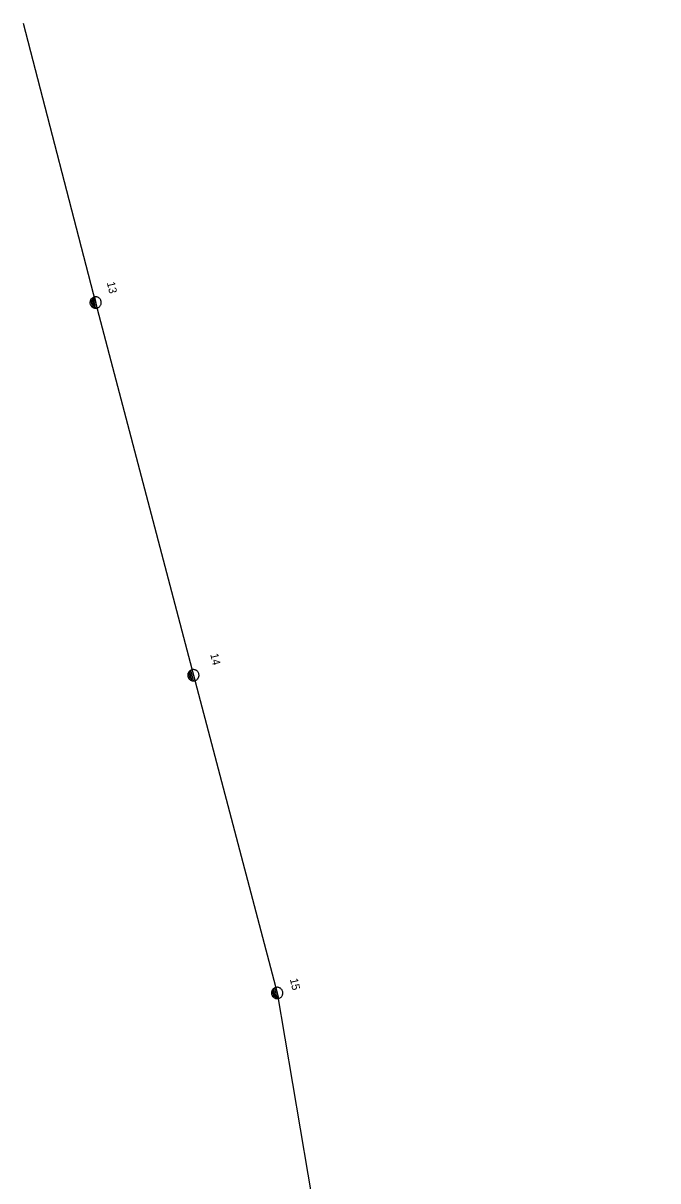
# Model space of a CAD drawing. Extents: x -762349 to -761250, y -1154000 to -1153000.
# Drawn here: x -761620.3 to -761482.3, y -1153251.6 to -1153000 of the extents above; entities that cross this region are included whole.
import ezdxf

# ---------------------------------------------------------------- set-up
doc = ezdxf.new("R2010")
doc.units = 0
for name, color, linetype in [('Vrstva 1', 7, 'Continuous'), ('Vrstva 13', 7, 'Continuous'), ('Vrstva 14', 7, 'Continuous')]:
    doc.layers.add(name, color=color, linetype=linetype)

msp = doc.modelspace()

# ---------------------------------------------------------------- linework, layer by layer
at = {"layer": 'Vrstva 1'}
msp.add_lwpolyline([(-761620.31, -1153000), (-761604.55, -1153060.72), (-761583.29, -1153141.72), (-761565.07, -1153210.77), (-761553.44, -1153279.72), (-761539.9, -1153359.95), (-761527.93, -1153428.59), (-761516.72, -1153491.97), (-761505.02, -1153559.26), (-761494.37, -1153619.64), (-761482.3, -1153689.6)], dxfattribs=at)
at = {"layer": 'Vrstva 13'}
for points in [[(-761604.279, -1153061.908), (-761604.155, -1153061.873), (-761604.036, -1153061.825), (-761603.922, -1153061.764), (-761603.815, -1153061.693), (-761603.717, -1153061.61), (-761603.628, -1153061.517), (-761603.549, -1153061.416), (-761603.48, -1153061.308), (-761603.424, -1153061.192), (-761603.38, -1153061.071), (-761603.349, -1153060.946), (-761603.331, -1153060.819), (-761603.327, -1153060.69), (-761603.336, -1153060.562), (-761603.358, -1153060.435), (-761603.393, -1153060.312), (-761603.442, -1153060.193), (-761603.502, -1153060.079), (-761603.574, -1153059.973), (-761603.656, -1153059.874), (-761603.749, -1153059.785), (-761603.85, -1153059.705), (-761603.959, -1153059.637), (-761604.075, -1153059.581), (-761604.196, -1153059.537), (-761604.32, -1153059.506), (-761604.448, -1153059.488), (-761604.576, -1153059.483), (-761604.704, -1153059.492), (-761604.831, -1153059.515), (-761604.955, -1153059.55), (-761605.074, -1153059.598), (-761605.188, -1153059.659), (-761605.294, -1153059.731), (-761605.393, -1153059.814), (-761605.482, -1153059.906), (-761605.561, -1153060.007), (-761605.629, -1153060.116), (-761605.686, -1153060.232), (-761605.73, -1153060.352), (-761605.761, -1153060.478), (-761605.779, -1153060.604), (-761605.783, -1153060.733), (-761605.774, -1153060.862), (-761605.752, -1153060.988), (-761605.716, -1153061.112), (-761605.668, -1153061.231), (-761605.608, -1153061.344), (-761605.536, -1153061.451), (-761605.453, -1153061.549), (-761605.361, -1153061.639), (-761605.259, -1153061.718), (-761605.15, -1153061.786), (-761605.035, -1153061.842), (-761604.914, -1153061.886), (-761604.789, -1153061.918), (-761604.662, -1153061.935), (-761604.533, -1153061.94), (-761604.405, -1153061.931), (-761604.279, -1153061.908)], [(-761605.39, -1153059.876), (-761604.945, -1153061.803)], [(-761605.148, -1153059.643), (-761604.634, -1153061.869)], [(-761604.824, -1153059.51), (-761604.272, -1153061.903)], [(-761605.61, -1153060.203), (-761605.29, -1153061.587)], [(-761583.019, -1153142.908), (-761582.895, -1153142.873), (-761582.776, -1153142.825), (-761582.662, -1153142.764), (-761582.555, -1153142.693), (-761582.457, -1153142.61), (-761582.368, -1153142.518), (-761582.289, -1153142.416), (-761582.22, -1153142.308), (-761582.164, -1153142.192), (-761582.12, -1153142.071), (-761582.089, -1153141.946), (-761582.071, -1153141.819), (-761582.067, -1153141.69), (-761582.076, -1153141.562), (-761582.098, -1153141.435), (-761582.133, -1153141.312), (-761582.182, -1153141.193), (-761582.242, -1153141.079), (-761582.314, -1153140.973), (-761582.396, -1153140.874), (-761582.489, -1153140.785), (-761582.59, -1153140.705), (-761582.7, -1153140.637), (-761582.815, -1153140.581), (-761582.936, -1153140.537), (-761583.06, -1153140.506), (-761583.188, -1153140.488), (-761583.316, -1153140.483), (-761583.445, -1153140.492), (-761583.571, -1153140.515), (-761583.695, -1153140.55), (-761583.814, -1153140.598), (-761583.928, -1153140.659), (-761584.034, -1153140.731), (-761584.133, -1153140.814), (-761584.222, -1153140.906), (-761584.301, -1153141.007), (-761584.369, -1153141.116), (-761584.426, -1153141.232), (-761584.47, -1153141.353), (-761584.501, -1153141.478), (-761584.519, -1153141.604), (-761584.523, -1153141.733), (-761584.514, -1153141.862), (-761584.492, -1153141.988), (-761584.456, -1153142.112), (-761584.408, -1153142.231), (-761584.348, -1153142.344), (-761584.276, -1153142.451), (-761584.194, -1153142.549), (-761584.101, -1153142.639), (-761583.999, -1153142.718), (-761583.89, -1153142.786), (-761583.775, -1153142.842), (-761583.654, -1153142.886), (-761583.53, -1153142.918), (-761583.402, -1153142.935), (-761583.273, -1153142.94), (-761583.145, -1153142.931), (-761583.019, -1153142.908)], [(-761583.565, -1153140.51), (-761583.012, -1153142.903)], [(-761584.35, -1153141.203), (-761584.03, -1153142.587)], [(-761584.13, -1153140.876), (-761583.685, -1153142.803)], [(-761583.888, -1153140.643), (-761583.374, -1153142.869)], [(-761564.799, -1153211.958), (-761564.675, -1153211.923), (-761564.556, -1153211.875), (-761564.442, -1153211.814), (-761564.335, -1153211.743), (-761564.237, -1153211.66), (-761564.148, -1153211.568), (-761564.069, -1153211.466), (-761564, -1153211.358), (-761563.944, -1153211.242), (-761563.9, -1153211.121), (-761563.869, -1153210.996), (-761563.851, -1153210.869), (-761563.847, -1153210.74), (-761563.856, -1153210.612), (-761563.878, -1153210.485), (-761563.913, -1153210.362), (-761563.962, -1153210.243), (-761564.022, -1153210.129), (-761564.094, -1153210.023), (-761564.176, -1153209.924), (-761564.269, -1153209.835), (-761564.37, -1153209.755), (-761564.48, -1153209.687), (-761564.595, -1153209.631), (-761564.716, -1153209.587), (-761564.84, -1153209.556), (-761564.968, -1153209.538), (-761565.096, -1153209.533), (-761565.225, -1153209.542), (-761565.351, -1153209.565), (-761565.475, -1153209.6), (-761565.594, -1153209.648), (-761565.708, -1153209.709), (-761565.814, -1153209.781), (-761565.913, -1153209.864), (-761566.002, -1153209.956), (-761566.081, -1153210.057), (-761566.149, -1153210.166), (-761566.206, -1153210.282), (-761566.25, -1153210.403), (-761566.281, -1153210.528), (-761566.299, -1153210.654), (-761566.303, -1153210.783), (-761566.294, -1153210.912), (-761566.272, -1153211.038), (-761566.236, -1153211.162), (-761566.188, -1153211.281), (-761566.128, -1153211.394), (-761566.056, -1153211.501), (-761565.974, -1153211.599), (-761565.881, -1153211.689), (-761565.779, -1153211.768), (-761565.67, -1153211.836), (-761565.555, -1153211.892), (-761565.434, -1153211.936), (-761565.31, -1153211.968), (-761565.182, -1153211.985), (-761565.053, -1153211.99), (-761564.925, -1153211.981), (-761564.799, -1153211.958)], [(-761566.13, -1153210.253), (-761565.81, -1153211.637)], [(-761565.91, -1153209.926), (-761565.465, -1153211.853)], [(-761565.668, -1153209.693), (-761565.154, -1153211.919)], [(-761565.344, -1153209.56), (-761564.792, -1153211.953)]]:
    msp.add_lwpolyline(points, dxfattribs=at)

# ---------------------------------------------------------------- texts
at = {"layer": 'Vrstva 14'}
for s, p in [('13', (-761602.12, -1153056.38)), ('14', (-761579.63, -1153137.16)), ('15', (-761562.32, -1153207.78))]:
    msp.add_text(s, height=1.74, rotation=283, dxfattribs=at).set_placement(p)

doc.saveas('drawing.dxf')
